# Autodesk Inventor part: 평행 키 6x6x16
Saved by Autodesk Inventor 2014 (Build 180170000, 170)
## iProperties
Created: 2025-12
Part Number: 평행 키 6x6x16
Material: 일반
Document SubType Name: Modeling
Designer: dg
Density: 1 g/cm^3
Appearance: 기본값
Author: dg
Author: jhkim
Description: 키 및 해당 키홈
Creation Date: 2025-11-19
Sending System: Autodesk Inventor 2026
Preprocessor: ST-DEVELOPER v20.1
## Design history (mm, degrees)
node "평행 키 6x6x161"
body "Solid1"
node "기준1"
